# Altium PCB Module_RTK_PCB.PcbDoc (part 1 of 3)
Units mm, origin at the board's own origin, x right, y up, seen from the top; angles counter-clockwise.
Board outline 99.98 x 60 mm, 4 copper layers (Top Layer, gnd, vcc, Bottom Layer), stack 1.536 mm thick; 168 components, 121 nets, 582 pads, 666 vias.
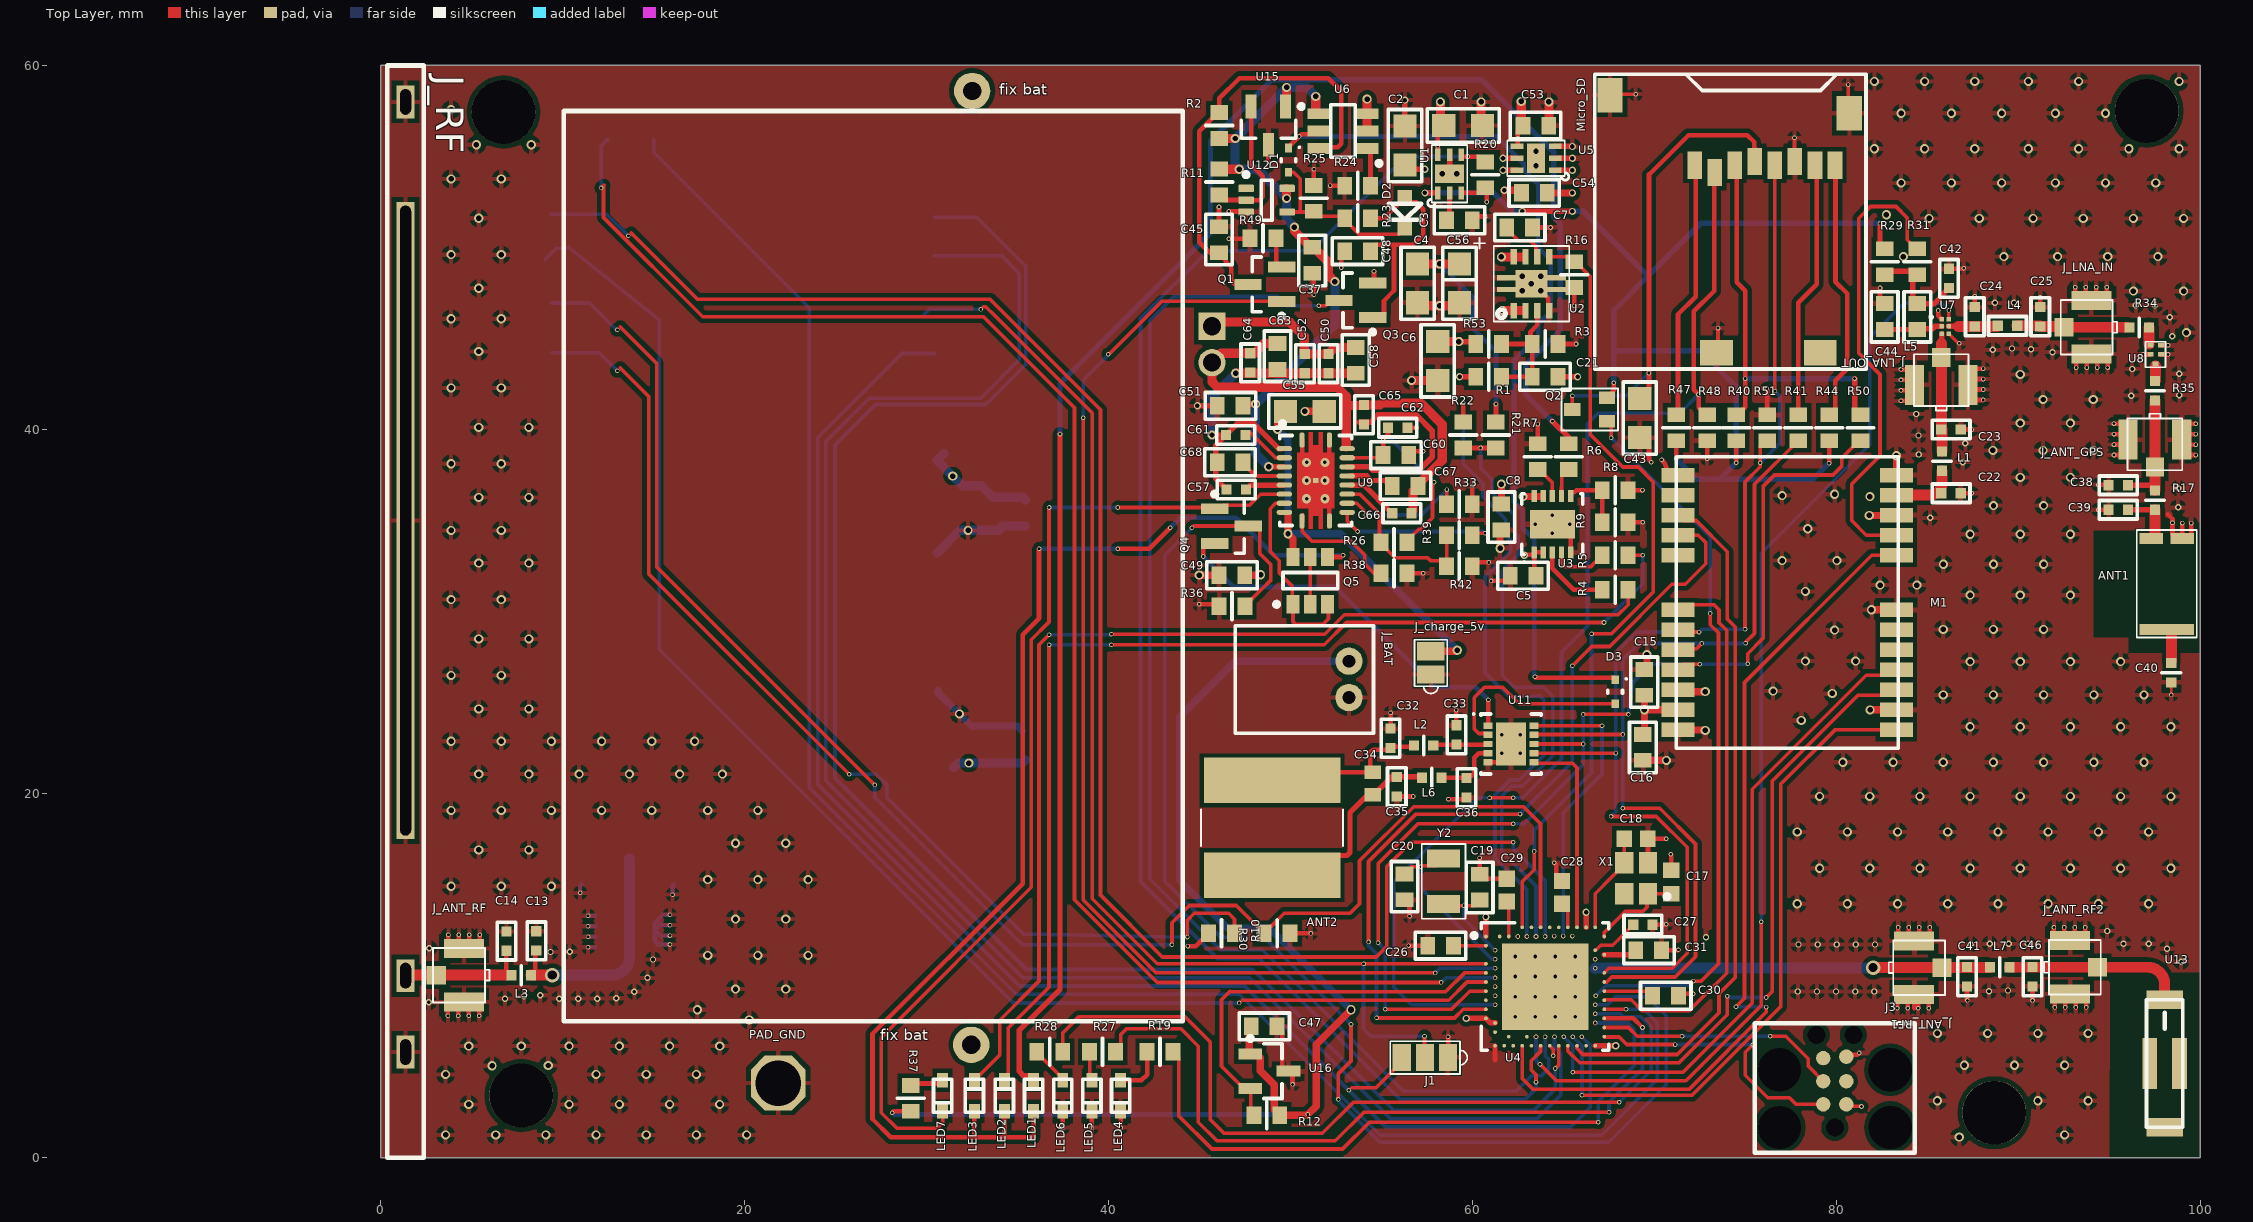
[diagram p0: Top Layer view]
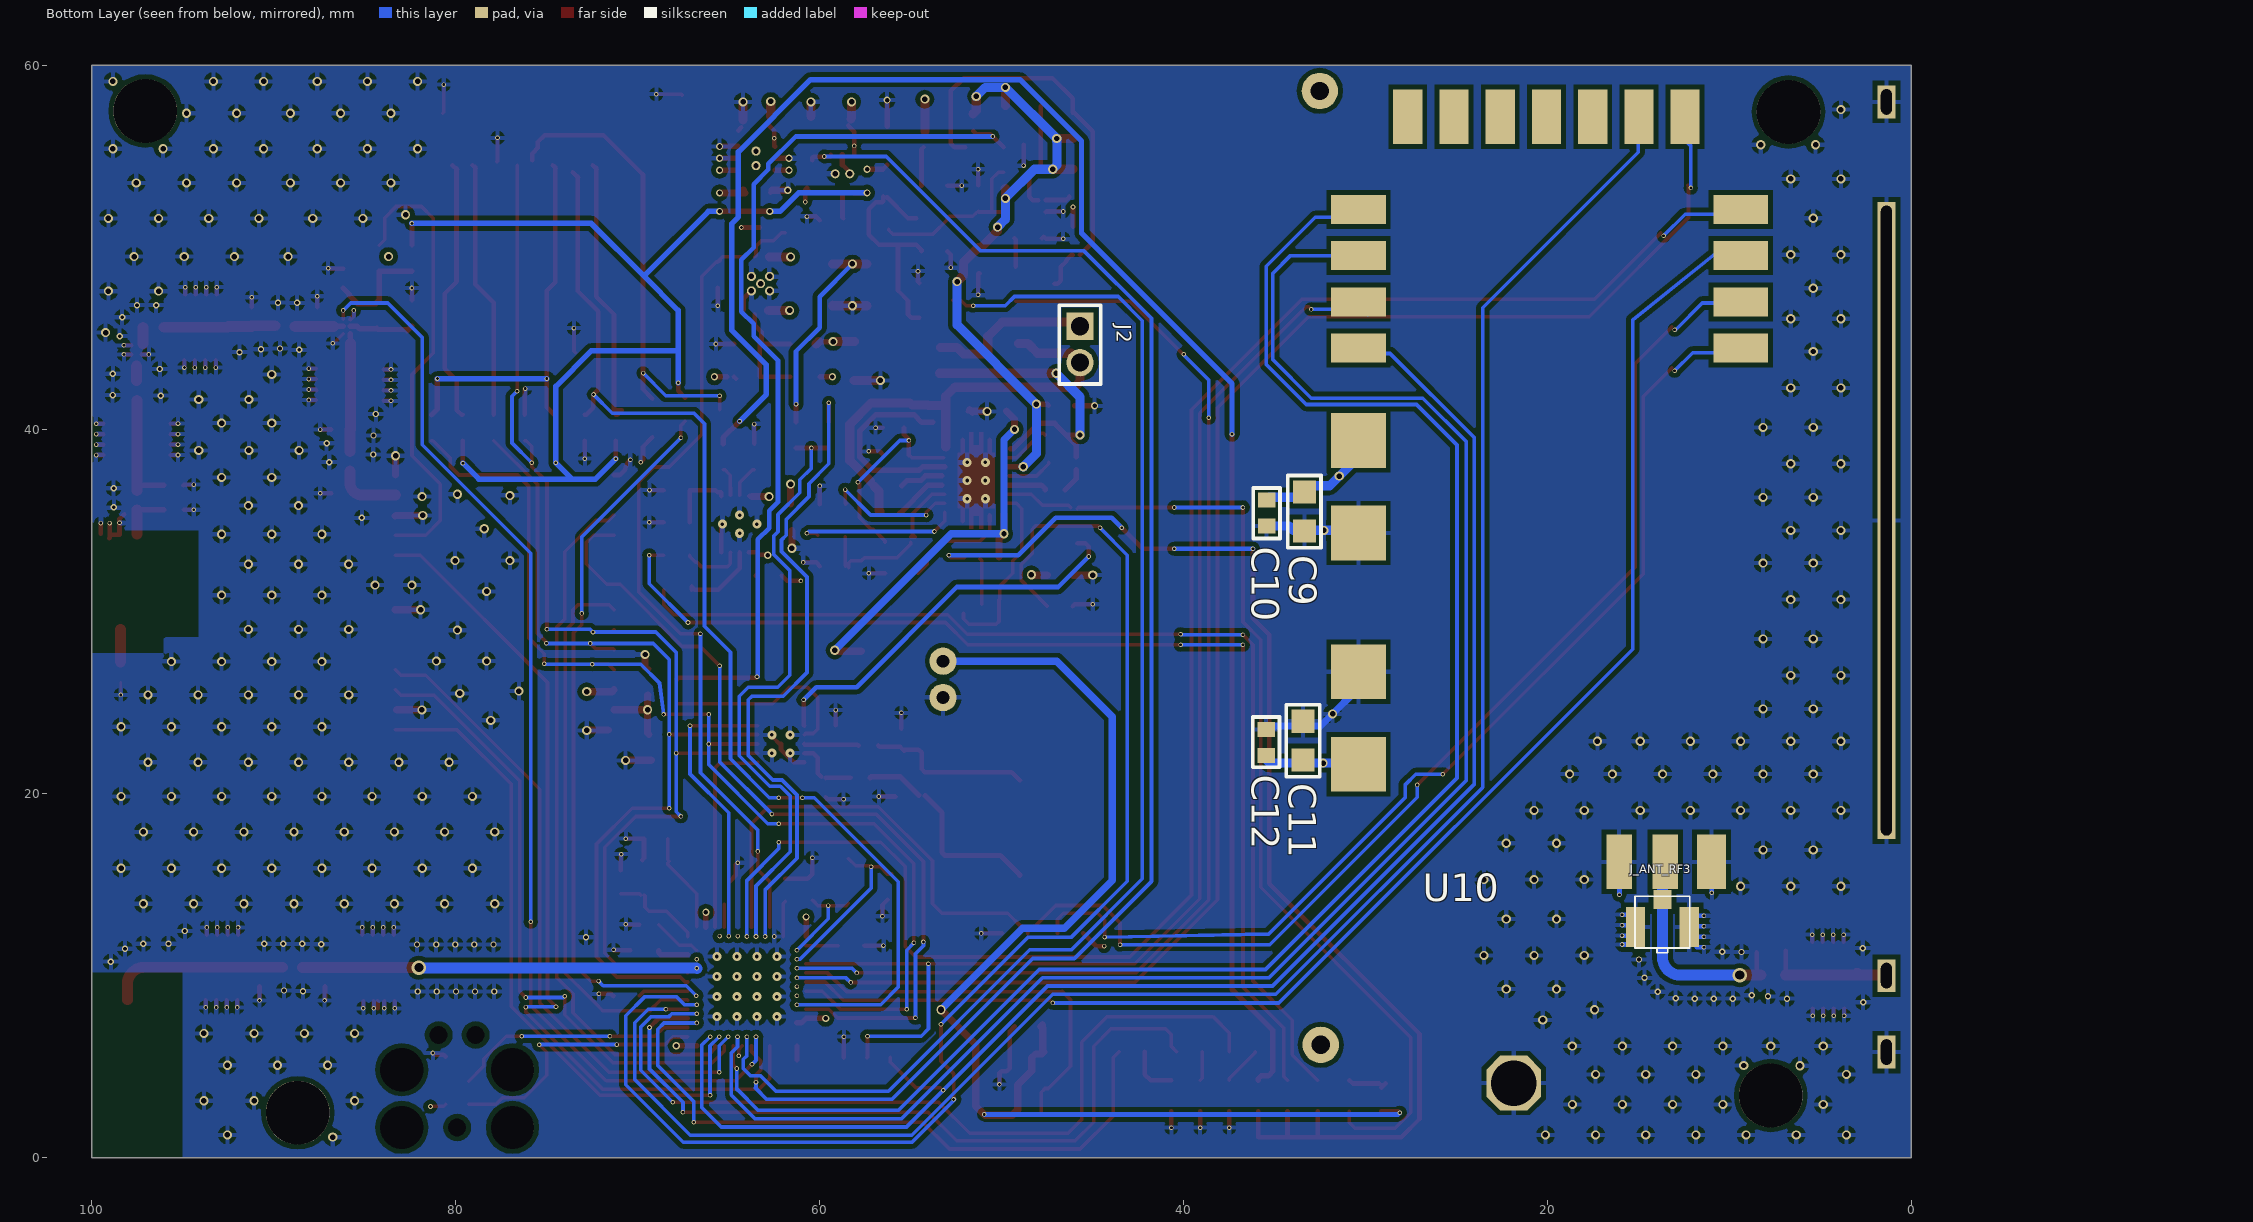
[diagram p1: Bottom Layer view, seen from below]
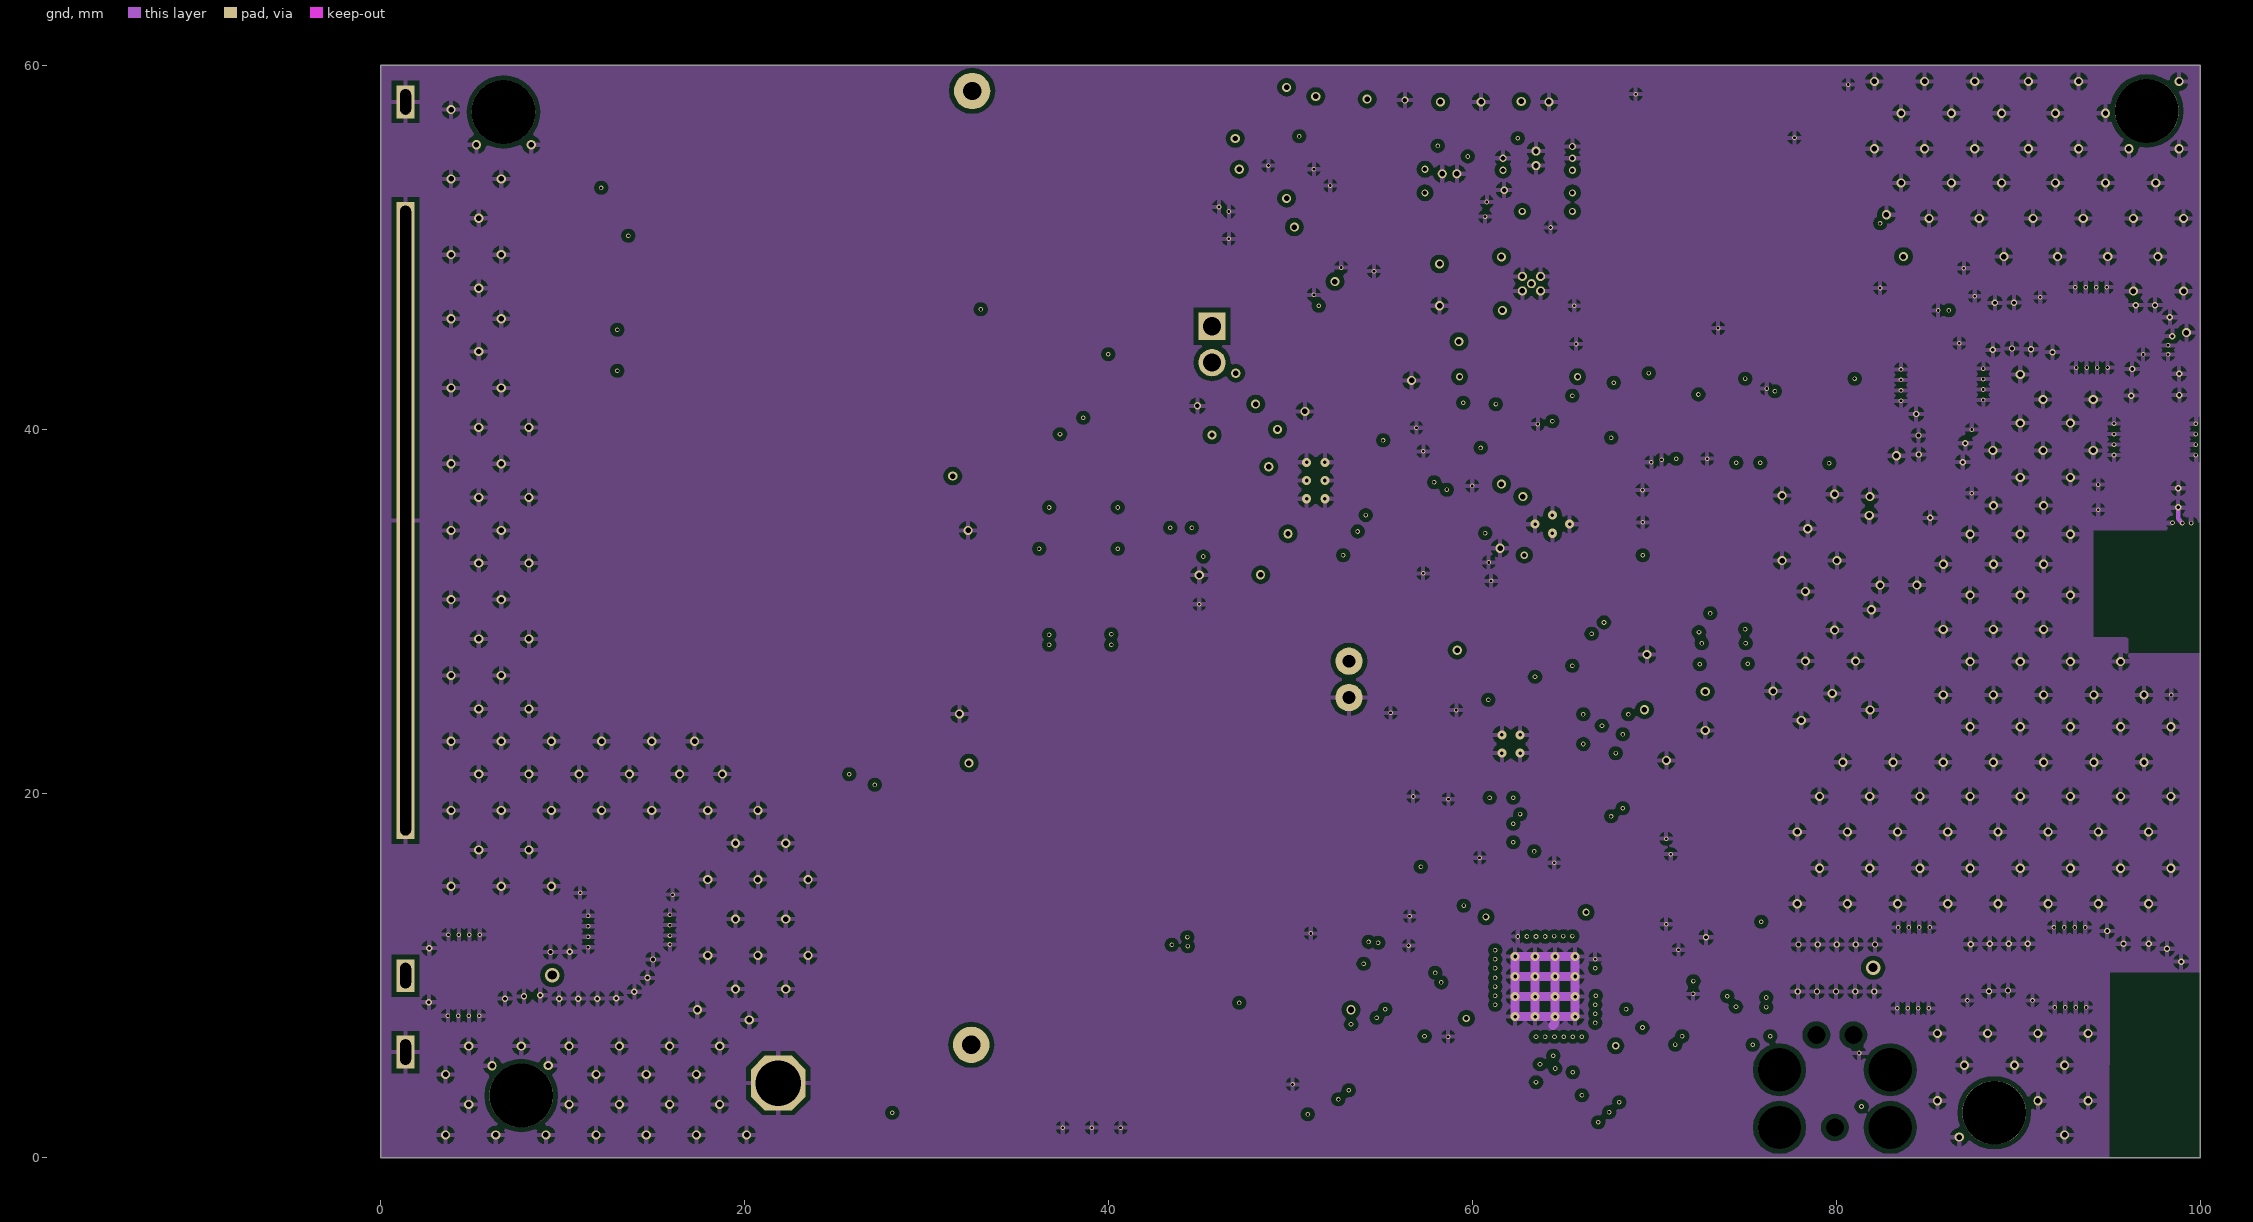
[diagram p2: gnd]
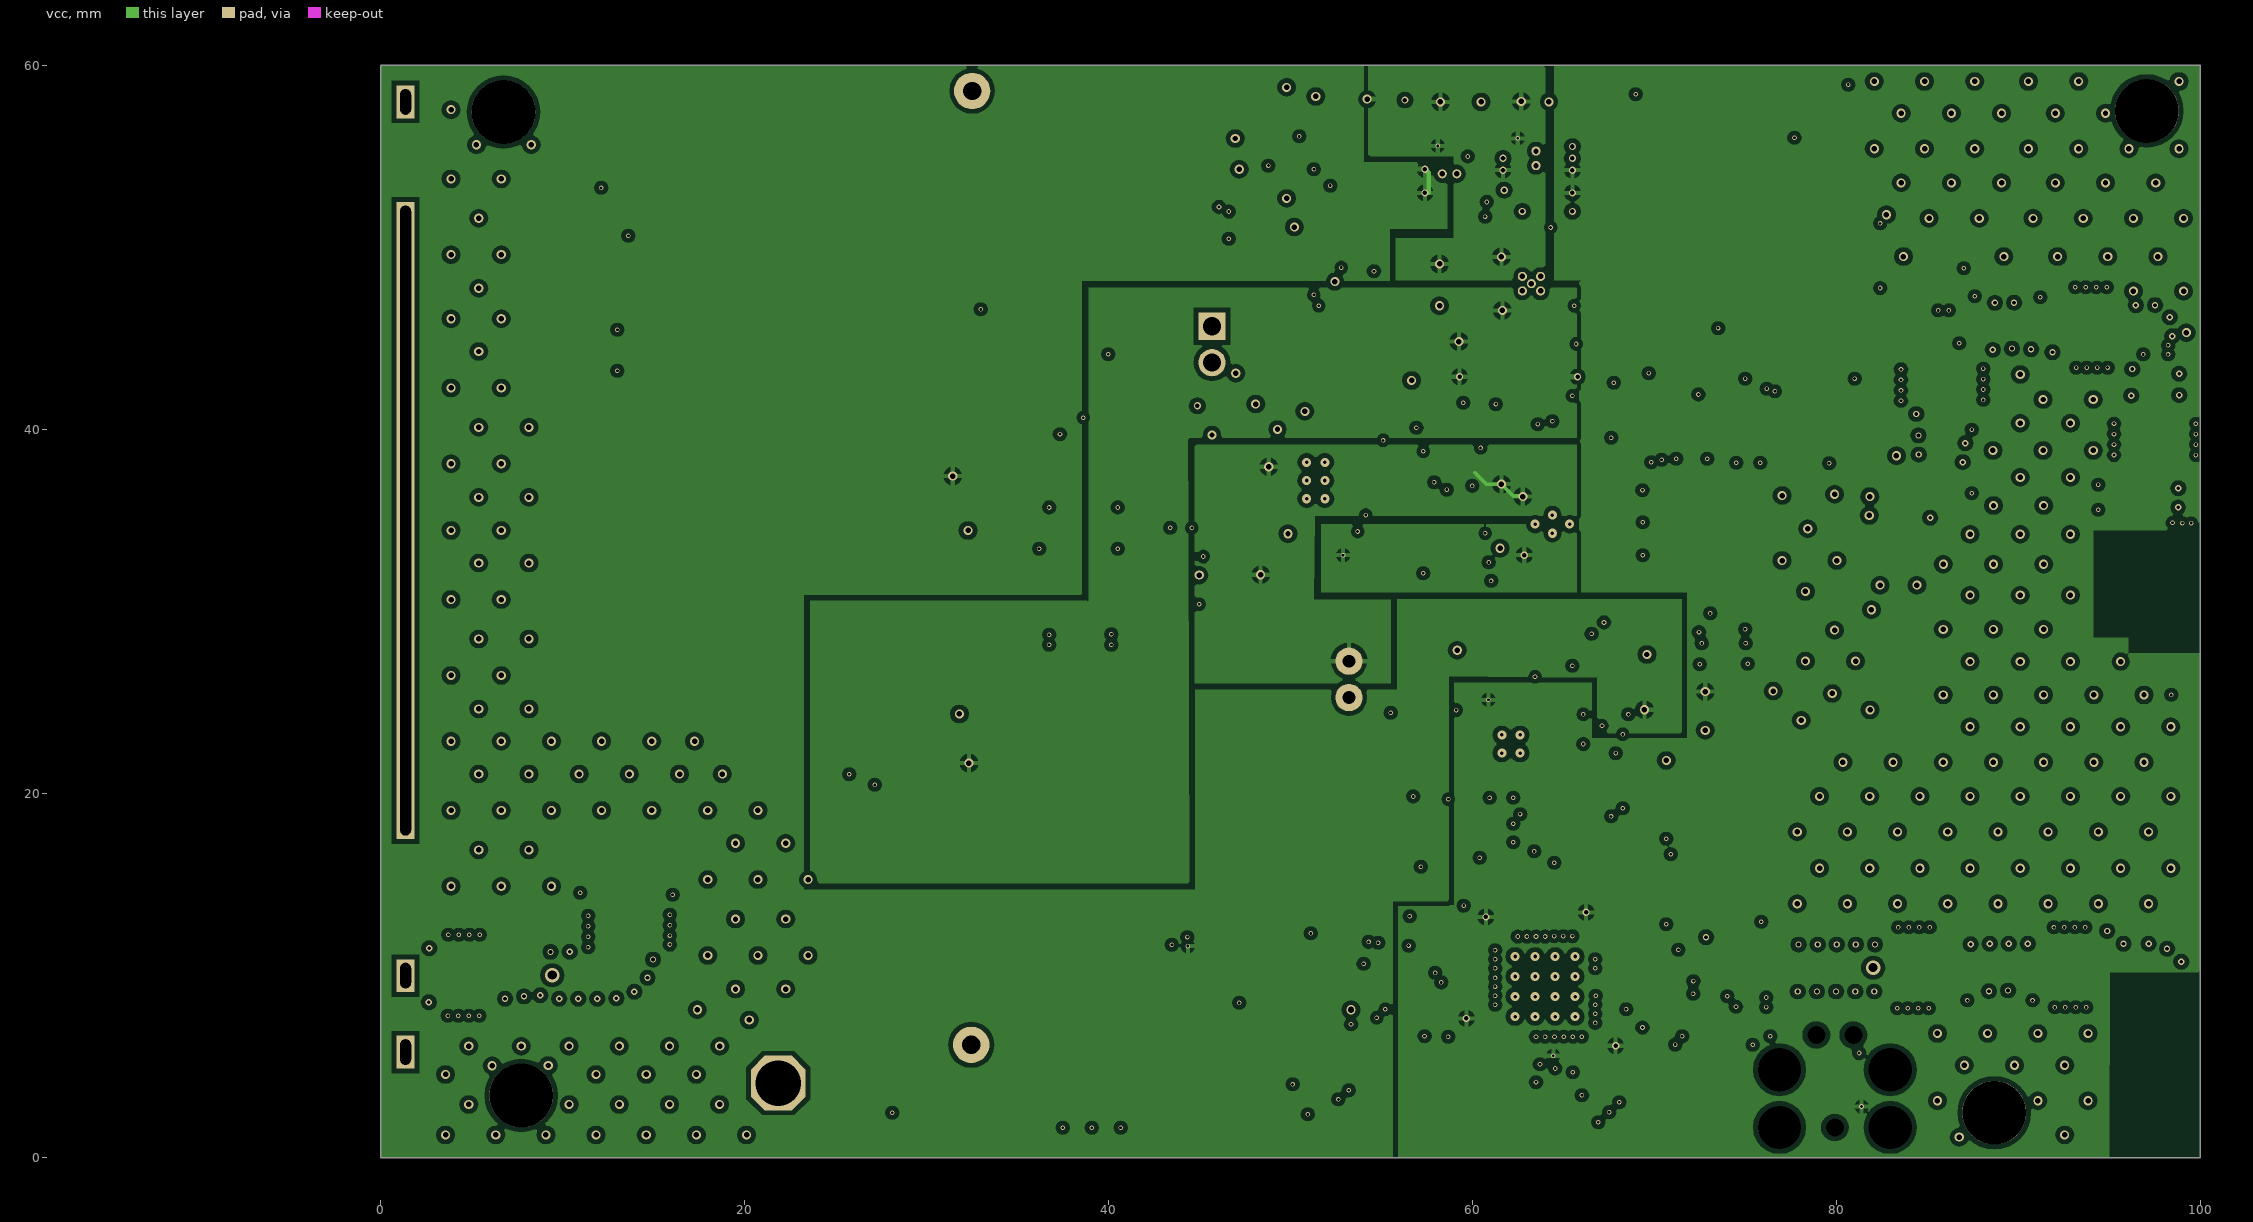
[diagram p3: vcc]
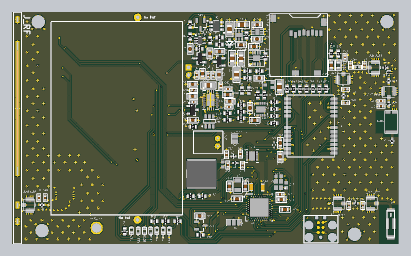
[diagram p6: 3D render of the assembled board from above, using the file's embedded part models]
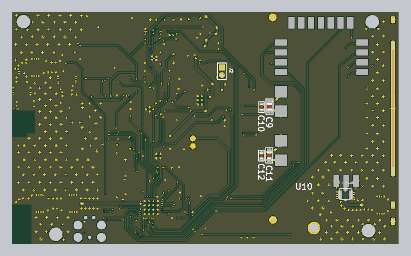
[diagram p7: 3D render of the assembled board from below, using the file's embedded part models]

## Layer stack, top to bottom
Top Solder: solder mask 0.01, Solder Resist, Dk 3.5
Top Layer: signal copper 0.018
Dielectric 2: prepreg 0.36, PP-006, Dk 3.9
gnd: signal copper 0.035
Dielectric 1: dielectric 0.71, FR-4, Dk 3.9
vcc: signal copper 0.035
Dielectric 3: prepreg 0.36, PP-006, Dk 3.9
Bottom Layer: signal copper 0.018
Bottom Solder: solder mask 0.01, Solder Resist, Dk 3.5

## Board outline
0,0 99.975,0 99.975,60 0,60
cut-out: -261.964,-109.154

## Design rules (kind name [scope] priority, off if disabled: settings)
Clearance Clearance_2 [InNet('NetC41_2') vs InNet('NetC46_2')] p1: gap=0.214 ignorepadtopadclearanceinfootprint=FALSE // pour ligne 50ohms de 600um (BLE)
Clearance Clearance_3 [InNet('AG_1') vs InNet('AG_2')] p2: gap=0.214 ignorepadtopadclearanceinfootprint=FALSE // pour ligne 50ohms de 600um (GPS)
Clearance Clearance_4 [InNet('AG_3') vs InNet('AG_4')] p3: gap=0.214 ignorepadtopadclearanceinfootprint=FALSE // pour ligne 50ohms de 600um (GPS)
Clearance Clearance_5 [InNet('AG_5') vs InNet('AG_6')] p4: gap=0.214 ignorepadtopadclearanceinfootprint=FALSE // pour ligne 50ohms de 600um (GPS)
Clearance Clearance_6 [InNet('AG_7') vs InNet('AG_8')] p5: gap=0.214 ignorepadtopadclearanceinfootprint=FALSE // pour ligne 50ohms de 600um (GPS)
Clearance Clearance_7 [InNet('NetANT1_3')] p6: gap=0.214 ignorepadtopadclearanceinfootprint=FALSE // pour ligne 50ohms de 600um (GPS)
Clearance Clearance_1 [InNet('ANT_1') vs InNet('ANT_2')] p7: gap=0.214 ignorepadtopadclearanceinfootprint=FALSE // pour ligne 50ohms de 600um (RF)
Clearance "Stitching GND" [IsStitchingVia and InNet('GND') vs (IsVia and (Not IsStitchingVia)) Or IsPad] p8: gap=0.214 ignorepadtopadclearanceinfootprint=FALSE
Clearance [All] p9: gap=0.254 ignorepadtopadclearanceinfootprint=FALSE except(0: Arc-Hole Track-Hole SMDPad-Hole THPad-Hole Via-Hole Fill-Hole Poly-Hole Region-Hole Text-Hole)
HoleSize [All] p1: absolutevalues=TRUE maxlimit=50 minlimit=0.025 maxpercent=80.000 minpercent=20.000
PolygonConnect [All] p1: connectstyle=Relief reliefconductorwidth=0.254 reliefentries=4 polygonreliefangle="90 Angle" airgapwidth=0.254
RoutingVias [All] p1: holewidth=0.15 width=0.25 viastyle="Through Hole" minholewidth=0.15 minwidth=0.25 maxholewidth=0.711 maxwidth=1.27
SolderMaskExpansion [All] p1: expansion=0.102
Width [All] p1 off: maxlimit=1.5 minlimit=0.2 preferedwidth=0.2
29 further rules are at their usual default settings.

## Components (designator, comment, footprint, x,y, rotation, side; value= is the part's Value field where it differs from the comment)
ANT1 "Taoglas-GLA.01" Taoglas-GLA.01 98.975,34.025 r270 top
ANT2 "W3102" W3102 48.975,18.125 r90 top
C1 "C-1uF-0805" SM/C_0805 59.475,56.7 r180 top value=1uF
C2 "C-2.2uF-0805" SM/C_0805 56.275,55.6 r270 top value=2.2uF
C3 "C-10nF-0603" SM/C_0603 59.264,51.5 r180 top value=10nF
C4 "C-1uF-0805" SM/C_0805 56.975,48.033 r90 top value=1uF
C5 "C-10uF-0603" SM/C_0603 62.769,31.971 r0 top value=10uF
C6 "C-4.7uF-0805" SM/C_0805 58.075,43.767 r90 top value=4.7uF
C7 "C-470nF-0603" SM/C_0603 62.575,51.1 r180 top value=470nF
C8 "C-10uF-0603" SM/C_0603 61.575,35.2 r90 top value=10uF
C9 "C-47uF-0805" SM/C_0805 33.35,35.492 r90 bottom value=47uF
C10 "C-100pF-0603" SM/C_0603 35.425,35.414 r90 bottom value=100pF
C11 "C-47uF-0805" SM/C_0805 33.425,22.906 r270 bottom value=47uF
C12 "C-100pF-0603" SM/C_0603 35.45,22.811 r270 bottom value=100pF
C13 "C-nc-0402" SM/C_0402 8.558,11.908 r270 top value=nc
C14 "C-nc-0402" SM/C_0402 6.912,11.9 r270 top value=nc
C15 "C-10uF-0603" SM/C_0603 69.425,26.111 r270 top value=10uF
C16 "C-100nF-0603" SM/C_0603 69.35,22.539 r90 top value=100nF
C17 "8pf" CAPC1608X90X35LL15T15 70.9,15.15 r90 top
C18 "8pf" CAPC1608X90X35LL15T15 68.975,17.525 r180 top
C19 "C-12pF-0603-2%-NP0" SM/C_0603 60.375,14.861 r90 top value=12pF
C20 "C-12pF-0603-2%-NP0" SM/C_0603 56.25,14.875 r270 top value=12pF
C21 "C-470nF-0603" SM/C_0603 63.975,42.9 r0 top value=470nF
C22 "C-nc-0402" SM/C_0402 86.275,36.5 r180 top value=nc
C23 "C-nc-0402" SM/C_0402 86.275,40 r180 top value=nc
C24 "C-nc-0402" SM/C_0402 87.575,46.2 r270 top value=nc
C25 "C-nc-0402" SM/C_0402 91.175,46.2 r270 top value=nc
C26 "C-100nF-0603" SM/C_0603 58.239,11.65 r0 top value=100nF
C27 "C-100pF 0402 NPO 5%" SM/C_0402 69.35,12.8 r0 top value=100pF
C28 "nc" CAPC1709X95X35LL10T25 64.9,14.575 r270 top
C29 "1uF" CAPC1709X95X35LL10T25 61.875,14.7 r270 top
C30 "C-100nF-0603" SM/C_0603 70.589,8.9 r180 top value=100nF
C31 "C-100nF-0603" SM/C_0603 69.664,11.4 r180 top value=100nF
C32 "C-nc-0402" SM/C_0402 55.487,23.037 r270 top value=nc
C33 "C-nc-0402" SM/C_0402 59.1,23.225 r270 top value=nc
C34 "06032U8R2CAT2A" CAPC1508X91X25LL25T13 54.5,20.545 r90 top value=8.2pf
C35 "C-nc-0402" SM/C_0402 55.825,20.375 r90 top value=nc
C36 "C-nc-0402" SM/C_0402 59.65,20.325 r90 top value=nc
C37 "C-100nF-0603" SM/C_0603 51.175,49.3 r90 top value=100nF
C38 "C-2.7pF-0402" SM/C_0402 95.467,36.938 r0 top value=2.7pF
C39 "C-nc-0402" SM/C_0402 95.467,35.592 r0 top value=nc
C40 "R-0-0402" SM/R_0402 98.375,26.642 r90 top value=0
C41 "C-nc-0402" SM/C_0402 87.15,9.938 r90 top value=nc
C42 "C-100pF-0402" SM/C_0402 86.154,48.3 r90 top value=100pF
C43 "C-47uF-0805" SM/C_0805 69.175,40.633 r90 top value=47uF
C44 "C-1uF-0603" SM/C_0603 82.625,46.207 r90 top value=1uF
C45 "C-10uF-0603" SM/C_0603 46.061,50.426 r270 top value=10uF
C46 "C-nc-0402" SM/C_0402 90.75,9.938 r90 top value=nc
C47 "C-100nF-0603" SM/C_0603 48.54,7.209 r180 top value=100nF
C48 "C-10uF-0603" SM/C_0603 53.675,49.8 r0 top value=10uF
C49 "C-100nF-0603" SM/C_0603 46.764,32 r180 top value=100nF
C50 "C-68n 0402 X7R" SM/C_0402 52.075,43.625 r270 top value=68n
C51 "C-4.7uF-0603" SM/C_0603 46.675,41.3 r180 top value=4.7uF
C52 "C-68n 0402 X7R" SM/C_0402 50.775,43.625 r270 top value=68n
C53 "C-1uF-0603" SM/C_0603 63.464,56.7 r0 top value=1uF
C54 "C-1uF-0603" SM/C_0603 63.386,53 r0 top value=1uF
C55 "C-1uF-0805" SM/C_0805 50.775,41 r180 top value=1uF
C56 "C-22uF-0805-6.3V-TANT" SM/C_0805_POL 59.275,48.033 r270 top value=22uF
C57 "C-22n 0402 X7R" SM/C_0402 47.008,36.7 r0 top value=22n
C58 "C-47n 0603 X7R" SM/C_0603 53.575,43.803 r270 top value=47n
C60 "C-4.7u 0603 X5R 16V" SM/C_0603 55.775,38.6 r180 top value=4.7u
C61 "C-10nF 0402 X7R 5%" SM/C_0402 46.975,39.7 r0 top value=10nF
C62 "C-22n 0402 X7R 16V" SM/C_0402 55.875,40.1 r180 top value=22n
C63 "C-1800pF 0603 NPO 5%" SM/C_0603 49.275,44.014 r270 top value=1800pF
C64 "C-100pF 0402 NPO 5%" SM/C_0402 47.775,43.658 r270 top value=100pF
C65 "C-10nF 0402 X7R 5%" SM/C_0402 54.025,40.818 r270 top value=10nF
C66 "C-22n 0402 X7R" SM/C_0402 56.108,35.4 r180 top value=22n
C67 "C-470nF-0603" SM/C_0603 56.286,36.9 r180 top value=470nF
C68 "C-470nF-0603" SM/C_0603 46.675,38.2 r0 top value=470nF
D1 "RB521S30T1G" ONSC-SOD-523-2-502-01_V 49.875,54.8 r270 top
D2 "D-CDSU4148-0603" 0603/SOD-523F_Diode 56.275,51.9 r270 top
D3 "RB521S30T1G" ONSC-SOD-523-2-502-01_V 67.825,25.6 r270 top
J1 "FTDI" SINGLE_3_1.27mm 58.645,5.5 r180 top
J2 "J-7.5uH  28X15mm Wurth 760308103206" WE-WPCC 45.675,45.675 r270 bottom
J3 "TC2030-CTX" TC2030-IDC 79.89,1.66 r90 top
J_ANT_GPS "U.FL-R-SMT" U.FL-R-SMT 97.475,37.938 r0 top
J_ANT_RF "U.FL-R-SMT" U.FL-R-SMT 3.058,10.025 r270 top
J_ANT_RF1 "U.FL-R-SMT" U.FL-R-SMT 85.776,10.438 r90 top
J_ANT_RF2 "U.FL-R-SMT" U.FL-R-SMT 94.325,10.463 r90 top
J_ANT_RF3 "U.FL-R-SMT" U.FL-R-SMT 13.684,14.187 r0 bottom
J_BAT "S2B-PH-K-S" S2B-PH-K-S 53.2,25.275 r90 top
J_charge_5v "charge 5v optionnel (fil a souder)" "2 pads soudable" 57.7,26.55 r90 top
J_LNA_IN "U.FL-R-SMT" U.FL-R-SMT 92.475,45.621 r270 top
J_LNA_OUT "U.FL-R-SMT" U.FL-R-SMT 85.742,43.965 r180 top
J_RF "FTDI" "connecteur ant RF" 2.375,0 r90 top
L1 "R-0-0402" SM/R_0402 85.775,38.267 r90 top value=0
L2 "R-0-0402" SM/R_0402 57.3,22.64 r0 top value=0
L3 "R-0-0402" SM/R_0402 7.725,10.025 r180 top value=0
L4 "L-4.7nH-0402" SM/L_0402 89.375,45.7 r0 top value=4.7nH
L5 "Lfe-60R-0603-1.2A" "SM/L_0603 (1608)" 84.425,46.207 r90 top value=Beads
L6 "R-0-0402" SM/R_0402 57.742,20.875 r0 top value=0
L7 "R-0-0402" SM/R_0402 88.95,10.463 r0 top value=0
LED1 "LED-RED-0603" SM/D_0603 35.875,3.4 r270 top
LED2 "LED-GREEN-0603" SM/D_0603 34.275,3.4 r270 top
LED3 "LED-ORANGE-0603" SM/D_0603 32.625,3.4 r270 top
LED4 "LED-RED-0603" SM/D_0603 40.654,3.4 r90 top
LED5 "LED-GREEN-0603" SM/D_0603 39.075,3.4 r90 top
LED6 "LED-AMBER-0603-HI_BRIGHT" SM/D_0603 37.475,3.4 r90 top
LED7 "LED-RED-0603" SM/D_0603 30.875,3.4 r90 top
M1 "NEO-M8P NEW!!" NEO-7 71.175,22.5 r0 top
Micro_SD "Micro_SD-Push_Push" Amphenol-10100660 72.2,54.525 r0 top
PAD_GND "Test_PAD_HOLE_3x3mm" Test_PAD_HOLE_3x3mm 21.85,4.1 r90 top
Q1 "BSS138" SOT23_0.915 48.583,47.975 r180 top
Q2 "PMOS" SOT-323 66.425,41.1 r90 top
Q3 "BSS138" SOT23_0.915 53.575,47.1 r180 top
Q4 "IRLML6402PBF" SOT23_0.915 46.75,34.7 r0 top
Q5 "FDC6304P" supersot_6 51.075,31.7 r90 top
R1 "R-62k-0603-0.1%" SM/R_0603 60.875,42.9 r180 top value=62k
R2 "R-100k-0603" SM/R_0603 46.075,56.7 r270 top value=100k
R3 "R-10k-0603-0.1%" SM/R_0603 63.975,44.7 r180 top value=10k
R4 "R-2.7k-0603" SM/R_0603 67.825,31.2 r180 top value=2.7k
R5 "R-2.7k-0603" SM/R_0603 67.825,33.1 r180 top value=2.7k
R6 "R-2.7k-0603" SM/R_0603 65.275,38.511 r270 top value=2.7k
R7 "R-10k-0603-0.1%" SM/R_0603 63.575,38.511 r270 top value=10k
R8 "R-10k-0603-0.1%" SM/R_0603 67.825,36.675 r180 top value=10k
R9 "R-10k-0603-0.1%" SM/R_0603 67.825,34.9 r180 top value=10k
R10 "R-10k-0603" SM/R_0603 46.2,12.323 r180 top value=10k
R11 "R-10k-0603" SM/R_0603 46.075,53.6 r270 top value=10k
R12 "R-10k-0603" SM/R_0603 48.689,2.325 r180 top value=10k
R16 "R-100k-0603" SM/R_0603 65.575,48.511 r90 top value=100k
R17 "R-0-0402" SM/R_0402 97.475,36.125 r270 top value=0
R19 "R-470-0603" SM/R_0603 42.822,5.825 r0 top value=470
R20 "R-100k-0603" SM/R_0603 60.675,53.989 r90 top value=100k
R21 "R-100k-0603-0.1%" SM/R_0603 61.275,39.7 r90 top value=100k
R22 "R-100k-0603-0.1%" SM/R_0603 59.475,39.7 r270 top value=100k
R23 "R-390k-0603" SM/R_0603 53.675,51.6 r180 top value=390k
R24 "R-10k-0603" SM/R_0603 53.675,53.4 r0 top value=10k
R25 "R-10k-0603" SM/R_0603 51.275,52.7 r90 top value=10k
R26 "R-20k-0603" SM/R_0603 55.675,33.8 r180 top value=20k
R27 "R-470-0603" SM/R_0603 39.664,5.825 r0 top value=470
R28 "R-100-0603" SM/R_0603 36.764,5.825 r0 top value=100
R29 "R-nc" SM/R_0603 82.625,49.218 r90 top value=nc
R30 "R-10k-0603" SM/R_0603 49.251,12.319 r180 top value=10k
R31 "R-0-0603" SM/R_0603 84.425,49.218 r270 top value=0
R33 "R-10k-0603" SM/R_0603 59.264,35.9 r0 top value=10k
R34 "R-0-0402" SM/R_0402 96.608,45.6 r0 top value=0
R35 "R-0-0402" SM/R_0402 97.475,42.125 r270 top value=0
R36 "R-470k-0603" SM/R_0603 46.775,30.3 r0 top value=470k
R37 "R-2.7k-0603" SM/R_0603 29.125,3.261 r270 top value=R-2.7k
R38 "R-2.43k-0603" SM/R_0603 55.675,32.1 r180 top value=2.43k
R39 "R-422-0603" SM/R_0603 59.264,34.2 r180 top value=422
R40 "R-10k-0603" SM/R_0603 74.475,40.1 r270 top value=10k
R41 "R-100-0603" SM/R_0603 77.875,40.1 r90 top value=100
R42 "R-200-0603" SM/R_0603 59.264,32.5 r180 top value=200
R44 "R-100k-0603" SM/R_0603 79.575,40.1 r90 top value=100k
R47 "R-100k-0603" SM/R_0603 71.175,40.1 r90 top value=100k
R48 "R-1M-0603" SM/R_0603 72.875,40.1 r270 top value=1M
R49 "R-10k-0603" SM/R_0603 48.475,50.5 r180 top value=10k
R50 "R-47-0603" SM/R_0603 81.3,40.1 r90 top value=47
R51 "R-1M-0603" SM/R_0603 76.175,40.1 r270 top value=1M
R53 "R-62k-0603-0.1%" SM/R_0603 60.875,44.7 r180 top value=62k
U1 "TPS73430DRV" SON-6_DRV 58.075,53 r90 top
U2 "TPS7A8101" SON-8_DRB 62.25,46.537 r90 top
U3 "MCP73833" DFN-MF10 64.375,34.8 r90 top
U4 "NRF52840-QIAA-R7" NRSC-AQFN-73 63.975,9.4 r0 top
U5 "TPS78230DRV" SON-6_DRV 64.525,54.25 r180 top
U6 "FDC6330L" SOT-363_0.95 52.875,56.4 r180 top
U7 "BGA725L6" INF-TSLP-6-2_V 85.954,45.667 r0 top
U8 "B9415" B9415 97.515,43.625 r90 top
U9 "BQ51050BRHLR" RHL20-3050X2050TP 51.375,37.2 r0 top
U10 "Module_RF_EXT_IO_4_2" Module_RF4_2 9.375,57.175 r270 bottom
U11 "AS3953A" MLPD_3x3mm_10_pin_AS3953A 62.1,22.725 r0 top
U12 "SN74LVC1G04DCKR" DCK0005A_N 48.675,52.6 r0 top
U13 "2450AT43B100" 2450AT43B100 98.01,5.176 r90 top
U15 "DRV5021" SOT23 48.775,56.7 r270 top
U16 "DRV5021" SOT23 48.825,4.75 r0 top
X1 "CX2520DB32000D0GEJZ1" AVX-CX2520DB32000D0GEJZ1-4_V 68.975,15.35 r180 top
Y2 "32.768kHz - 20ppm - CTS-TF32" CTS-TF32 58.4,15.18 r90 top

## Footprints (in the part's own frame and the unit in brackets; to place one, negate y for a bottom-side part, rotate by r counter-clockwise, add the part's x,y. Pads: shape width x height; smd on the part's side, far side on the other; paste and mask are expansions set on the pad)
"2 pads soudable" [mm] "Connector; Header; 2 Position"
  rect 1x1.5 smd: 1(0,0) 2(1.27,0)
  silkscreen extent -1.05,-0.9 1.91,0.9
0603/SOD-523F_Diode [mm] "SODFL, 2-Leads, Body 0,90x1,70mm, IPC Medium Density"
  rect 0.8x0.8 smd: 1(-0.85,0) 2(0.85,0)
  silkscreen extent -0.51,-0.89 0.38,0.89, body extent -0.9,-0.5 0.9,0.5, height 0.85
2450AT43B100 [mm] "ble ant 2.4 GHz"
  rect 1x2 smd: 1(3.5,0) 2(-3.5,0)
  rect 2.8x0.8 smd: 3(0,0.815) 4(0,-0.815)
  silkscreen extent -3.5,-1 3.5,1
Amphenol-10100660 [mm] "Micro-SD"
  rect 1.4x1.9 smd: 0(-4.66,3.85) 0(8.49,2.85)
  rect 1.8x1.4 smd: 0(1.19,-10.3) 9(6.89,-10.3)
  rect 0.8x1.5 smd: 1(0,0) 2(1.1,-0.4) 3(2.2,0) 4(3.3,0.2) 5(4.4,0) 6(5.5,0.2) 7(6.6,0) 8(7.7,0)
  silkscreen extent -5.5,-11.2 9.4,5
AVX-CX2520DB32000D0GEJZ1-4_V [mm] "Hand Drawn, 4-Leads,Body 2.5x2mm"
  rect 1x1.2 smd: 1(-0.65,0.85) 2(-0.65,-0.85) 3(0.65,-0.85) 4(0.65,0.85)
  silkscreen extent -1.83,0.88 -1.58,1.12, body extent -1,-1.25 1,1.25, height 0.55
B9415 [mm]
  rect 0.25x0.325 smd: 1(0,0) 2(0.5,-0.288) 3(1,-0.288) 4(1,0.288) 5(0.5,0.288)
  silkscreen extent -0.2,-0.55 1.2,0.55
CAPC1508X91X25LL25T13 [mm] "Chip Capacitor, 2-Leads, Body 1.52x0.76mm, IPC High Density"
  rect 0.74x0.92 smd: 1(-0.62,0) 2(0.62,0)
  body extent -0.88,-0.51 0.89,0.51, height 0.91
CAPC1608X90X35LL15T15 [mm] "Chip Capacitor, 2-Leads, Body 1.60x0.81mm, IPC High Density"
  rect 0.85x0.9 smd: 1(-0.65,0) 2(0.65,0)
  body extent -0.88,-0.48 0.87,0.48, height 0.9
CAPC1709X95X35LL10T25 [mm] "Chip Capacitor, 2-Leads, Body 1.75x0.95mm, IPC High Density"
  rect 0.9x0.9 smd: 1(-0.625,0) 2(0.625,0)
  body extent -0.87,-0.48 0.87,0.48, height 0.95
"connecteur ant RF" [mm]
  rect 1.8x1 hole 0.6 slot 1.4 at 0 deg: 1(10,1) 2(5.8,1) 3(58,1)
  rect 35x1 hole 0.6 slot 34.6 at 0 deg: 2(35,1)
  silkscreen extent 0,0 60,2
CTS-TF32 [mm] "3.2mm x 1.5mm"
  rect 1x1.8 smd: 1(-1.25,0) 2(1.25,0)
  silkscreen extent -2.05,-1.2 2.05,1.2
DCK0005A_N [mm] "SOT23, 5-Leads, Body 2.15x1.4mm, Pitch 0.65mm, IPC Medium Density"
  rrect25% 0.85x0.4 smd: 1(-1.125,0.65) 2(-1.125,0) 3(-1.125,-0.65) 4(1.125,-0.65) 5(1.125,0.65)
  silkscreen extent -1.25,-1.1 0.3,1.52, body extent -1.14,-1 1.14,1, height 0.94
DFN-MF10 [mm] "SON, 10-Leads, Body 3x3mm, Pitch 0.5mm, Microchip Recommended"
  rect 1.55x2.48 smd: 0(0,0)
  rect 0.65x0.3 smd: 1(-1.55,1) 2(-1.55,0.5) 3(-1.55,0) 4(-1.55,-0.5) 5(-1.55,-1) 6(1.55,-1) 7(1.55,-0.5) 8(1.55,0) 9(1.55,0.5) 10(1.55,1)
  silkscreen extent -2.12,-1.68 1.67,1.68, body extent -1.52,-1.52 1.52,1.52, height 1
INF-TSLP-6-2_V [mm] "TSLP, 6-Leads, Body 0.7x1.1 mm"
  rect 0.25x0.25 smd: 1(-0.2,0.4) 2(-0.2,0) 3(-0.2,-0.4) 4(0.2,-0.4) 5(0.2,0) 6(0.2,0.4)
  silkscreen extent -0.8,0.48 -0.75,0.53, body extent -0.35,-0.55 0.35,0.55, height 0.4
MLPD_3x3mm_10_pin_AS3953A [mm] "PSON, 10-Leads, Body 3,00x3,00mm, Pitch 0,50mm, Thermal Pad 2,36x1,63mm, IPC Medium Density"
  rect 0.5x0.35 smd: 1(-1.27,1) 2(-1.27,0.5) 3(-1.27,0) 4(-1.27,-0.5) 5(-1.27,-1) 6(1.27,-1) 7(1.27,-0.5) 8(1.27,0) 9(1.27,0.5) 10(1.27,1)
  rect 1.63x2.36 smd: 11(0,0)
  silkscreen extent -2.1,-1.65 1.65,1.7, body extent -1.5,-1.5 1.5,1.5, height 1
Module_RF4_2 [mm]
  rect 3x3 smd: 1(35.56,-21) 2(30.48,-21) 3(22.86,-21) 4(17.78,-21)
  rect 1.6x3 smd: 5(12.7,-21) 6(10.16,-21) 7(7.62,-21) 8(5.08,-21) 16(5.08,0) 17(7.62,0) 18(10.16,0) 19(12.7,0)
  rect 3x1.6 smd: 9(0,-18.296) 10(0,-15.756) 11(0,-13.216) 12(0,-10.676) 13(0,-8.136) 14(0,-5.596) 15(0,-3.056) 20(40.925,-1.61)
  rect 3x1.4 smd: 21(40.925,-4.15) 22(40.925,-6.69)
  body extent 0.13,-20.96 40.93,0, height 3
NEO-7 [mm] "GNSS module for GPS/QZSS, GLONASS"
  rect 1.8x0.8 smd: 1(12.1,1) 2(12.1,2.1) 3(12.1,3.2) 4(12.1,4.3) 5(12.1,5.4) 6(12.1,6.5) 7(12.1,7.6) 8(12.1,10.6) 9(12.1,11.7) 10(12.1,12.8) 11(12.1,13.9) 12(12.1,15) 13(0.1,15) 14(0.1,13.9) 15(0.1,12.8) 16(0.1,11.7) 17(0.1,10.6) 18(0.1,7.6) 19(0.1,6.5) 20(0.1,5.4) 21(0.1,4.3) 22(0.1,3.2) 23(0.1,2.1) 24(0.1,1)
  silkscreen extent 0,0 12.2,16
NRSC-AQFN-73 [mm] "AQFN, 73-Leads, Body 7x7mm, Pitch 0.5mm"
  rect 4.75x4.75 smd: 74(0,0)
  round 0.2 smd: A8(-1.25,3.25) A10(-0.75,3.25) A12(-0.25,3.25) A14(0.25,3.25) A16(0.75,3.25) A18(1.25,3.25) A20(1.75,3.25) A22(2.25,3.25) A23(2.75,3.25) AA24(3.25,-2.25) AB2(-2.75,-2.5) AC5(-2,-2.75) AC9(-1,-2.75) AC11(-0.5,-2.75) AC13(0,-2.75) AC15(0.5,-2.75) AC17(1,-2.75) AC19(1.5,-2.75) AC21(2,-2.75) AC24(3.25,-2.75) AD2(-2.75,-3.25) AD4(-2.25,-3.25) AD6(-1.75,-3.25) AD8(-1.25,-3.25) AD10(-0.75,-3.25) AD12(-0.25,-3.25) AD14(0.25,-3.25) AD16(0.75,-3.25) AD18(1.25,-3.25) AD20(1.75,-3.25) AD22(2.25,-3.25) AD23(2.75,-3.25) B1(-3.25,2.75) B3(-2.5,2.75) B5(-2,2.75) B7(-1.5,2.75) B9(-1,2.75) B11(-0.5,2.75) B13(0,2.75) B15(0.5,2.75) B17(1,2.75) B19(1.5,2.75) B24(3.25,2.75) C1(-3.25,2.25) D2(-2.75,2) D23(2.75,2) E24(3.25,1.75) F2(-2.75,1.5) F23(2.75,1.5) G1(-3.25,1.25) H2(-2.75,1) H23(2.75,1) J1(-3.25,0.75) J24(3.25,0.75) K2(-2.75,0.5) L1(-3.25,0.25) L24(3.25,0.25) M2(-2.75,0) N1(-3.25,-0.25) N24(3.25,-0.25) P2(-2.75,-0.5) P23(2.75,-0.5) R1(-3.25,-0.75) R24(3.25,-0.75) T2(-2.75,-1) T23(2.75,-1) U1(-3.25,-1.25) U24(3.25,-1.25) V23(2.75,-1.5) W1(-3.25,-1.75) W24(3.25,-1.75) Y2(-2.75,-2) Y23(2.75,-2)
  silkscreen extent -4.02,-3.5 3.5,3.5, body extent -3.5,-3.5 3.5,3.5, height 0.85
ONSC-SOD-523-2-502-01_V [mm] "SOD, 2-Leads, Body 1.2x0.8mm"
  rect 0.48x0.4 smd: 1(-0.66,0) 2(0.66,0)
  silkscreen extent -0.75,-0.4 0.07,0.65, body extent -0.6,-0.4 0.6,0.4, height 0.7
RHL20-3050X2050TP [mm] "QFN, 20-Leads, Body 4.5x3.5mm, Pitch 0.5mm, Thermal Pad 3.05x2.05mm, TI Recommended"
  oval 0.28x0.85 smd paste-0.025 mask+0.07: 1(-0.75,2.225) 10(-0.75,-2.225) 11(0.75,-2.225) 20(0.75,2.225)
  oval 0.85x0.28 smd paste-0.025 mask+0.07: 2(-1.725,1.75) 3(-1.725,1.25) 4(-1.725,0.75) 5(-1.725,0.25) 6(-1.725,-0.25) 7(-1.725,-0.75) 8(-1.725,-1.25) 9(-1.725,-1.75) 12(1.725,-1.75) 13(1.725,-1.25) 14(1.725,-0.75) 15(1.725,-0.25) 16(1.725,0.25) 17(1.725,0.75) 18(1.725,1.25) 19(1.725,1.75)
  rect 0.3x0.3 smd paste-0.15 mask+0: 21(0,0)
  Top Layer region: 0.16,2.65 0.16,1.925 -0.16,1.925 -0.16,2.65 -0.39,2.65 -0.39,1.525 -1.025,1.525 -1.025,-1.525 -0.39,-1.525 -0.39,-2.65 -0.16,-2.65 -0.16,-1.925 0.16,-1.925 0.16,-2.65 0.39,-2.65 0.39,-1.525 1.025,-1.525 1.025,1.525 0.39,1.525 0.39,2.65
  silkscreen extent -1.97,-2.48 1.98,3.25, body extent -1.82,-2.33 1.83,2.32, height 1
S2B-PH-K-S [mm]
  round 1.5 hole 0.7: 1(0,0) 2(2,0)
  silkscreen extent -1.95,-1.35 3.95,6.25
SINGLE_3_1.27mm [mm] "Connector; Header; 3 Position"
  rect 1x1.5 smd: 1(0,0) 2(1.27,0) 3(2.54,0)
  silkscreen extent -1.05,-0.9 3.17,0.9
SM/C_0402 [mil]
  rect 22x22 smd: 1(-21,0) 2(21,0)
  silkscreen extent -41,-20 41,20, body extent -20,-10 20,10, height 20
SM/C_0603 [mil]
  rect 32x38 smd: 1(-28,0) 2(28,0)
  silkscreen extent -55,-29 54,29, body extent -31,-16 31,15, height 31
SM/C_0805 [mil]
  rect 50x50 smd: 1(-42,0) 2(42,0)
  silkscreen extent -78,-36 78,36, body extent -39,-24 39,23, height 47
SM/C_0805_POL [mil]
  rect 50x50 smd: 1(-42,0) 2(42,0)
  silkscreen extent -98,-36 78,55, body extent -39,-24 39,23, height 47
SM/D_0603 [mm] "Diode Package 0603"
  rect 0.8x0.6 smd: 1(0.85,0) 2(-0.85,0)
  silkscreen extent -0.9,-0.5 0.9,0.5, body extent -0.9,-0.5 0.9,0.5, height 0.85
SM/L_0402 [mil]
  rect 22x22 smd: 1(-21,0) 2(21,0)
  silkscreen extent -41,-20 41,20, body extent -20,-10 20,10, height 20
"SM/L_0603 (1608)" [mil]
  rect 32x38 smd: 1(-28,0) 2(28,0)
  silkscreen extent -55,-29 54,29, body extent -31,-16 32,16, height 35
SM/R_0402 [mil]
  rect 22x22 smd: 1(-21,0) 2(21,0)
  silkscreen extent 0,-20 0,20, body extent -19,-10 20,10, height 15
SM/R_0603 [mil]
  rect 32x38 smd: 1(-28,0) 2(28,0)
  silkscreen extent 0,-29 0,29, body extent -31,-16 32,16, height 21
SON-6_DRV [mm] "SON-6 DRV (TPS73533)"
  round 0.5 hole 0.3: 0(1.05,-1.05) 0(1.05,-0.25)
  rect 1x1.6 smd: 0(1.05,-0.65)
  rect 0.7x0.3 smd: 1(0,0) 2(0,-0.65) 3(0,-1.3) 4(2.1,-1.3) 5(2.1,-0.65) 6(2.1,0)
  silkscreen extent -0.75,-1.63 2.63,0.55
SON-8_DRB [mm] "SON-8 DRB (TPS7A8001)"
  round 0.5 hole 0.3: 0(1.075,-0.475) 0(1.075,-1.475) 0(1.475,-0.975) 0(1.875,-1.475) 0(1.875,-0.475)
  rect 0.28x1.225 smd: 0(1.15,0.313) 0(1.15,-2.263) 0(1.8,0.313)
  rect 1.5x1.75 smd: 0(1.475,-0.975)
  rect 0.28x1.225 smd paste+0: 0(1.8,-2.263)
  rect 0.85x0.35 smd: 1(0,0) 2(0,-0.65) 3(0,-1.3) 4(0,-1.95) 5(2.95,-1.95) 6(2.95,-1.3) 7(2.95,-0.65) 8(2.95,0)
  silkscreen extent -0.6,-3.05 3.55,1.1
SOT23 [mm] "SOT23, 3-Leads, Body 2,90x2,45mm, Pitch 0,95mm, IPC Medium Density"
  rect 1.3x0.6 smd: 1(-1.05,0.95) 2(-1.05,-0.95) 3(1.05,0)
  silkscreen extent -1.17,-1.5 0.7,1.93, body extent -0.7,-1.5 0.7,1.5, height 1.1
SOT23_0.915 [mm]
  rect 1.5x0.6 smd: 1(-0.925,0.95) 2(-0.925,-0.95) 3(0.925,0)
  silkscreen extent -1.05,-1.5 0.7,1.87, body extent -1.4,-1.45 1.4,1.45, height 1.3
SOT-323 [mm]
  rect 0.7x0.9 smd: 1(-0.65,-0.95) 2(0.65,-0.95) 3(0,0.95)
  silkscreen extent -1.15,-1.55 1.15,1.55
SOT-363_0.95 [mm] "TSOT-23, 6-Leads, Body 2.90x1.63mm, Pitch 0.95mm, IPC Medium Density"
  rect 1.25x0.6 smd: 1(-1.325,0.95) 2(-1.325,0) 3(-1.325,-0.95) 4(1.325,-0.95) 5(1.325,0) 6(1.325,0.95)
  silkscreen extent -2.1,-1.45 0.67,1.9, body extent -1.43,-1.45 1.4,1.45, height 1
supersot_6 [mm]
  rect 1x0.7 smd: 1(-1.3,0.95) 2(-1.3,0) 3(-1.3,-0.95) 4(1.3,-0.95) 5(1.3,0) 6(1.3,0.95)
  silkscreen extent -1.42,-1.5 0.45,1.97, body extent -0.84,-1.5 0.84,1.5, height 1.1
Taoglas-GLA.01 [mm]
  rect 0.6x1.3 smd: 1(0,0) 2(0,-1.7)
  rect 0.6x3 smd: 3(5,-0.85)
  silkscreen extent -0.45,-2.5 5.45,0.8
TC2030-IDC [mm]
  round 2.3 hole 2.375 unplated: 0(0,3.04) 0(0,-3.04) 0(3.175,3.04) 0(3.175,-3.04)
  round 0.9 hole 0.995 unplated: 0(0,0) 0(5.08,-1.016) 0(5.08,1.016)
  round 0.79 smd paste-0.6: 1(1.27,-0.635) 2(1.27,0.635) 3(2.54,-0.635) 4(2.54,0.635) 5(3.89,-0.635) 6(3.81,0.635)
  silkscreen extent -1.4,-4.4 5.71,4.4
Test_PAD_HOLE_3x3mm [mm]
  oct 3x3 hole 2.5: 0(0,0)
U.FL-R-SMT [mm]
  rect 1x1.05 smd: 1(0,0)
  rect 1.05x2.2 smd: 2(-1.475,1.525) 2(1.475,1.525)
  silkscreen extent -1.5,-0.18 1.5,2.92
W3102 [mm]
  rect 2.5x7.5 smd: 1(-2.6,0) 2(2.6,0)
  silkscreen extent -1,-3.9 1,3.9, body extent -3.6,-3.9 3.6,3.9, height 5.45
WE-WPCC [mm] "Wireless Power Charging  Receiver Coil"
  rect 1.5x1.5 hole 1: 1(0,0)
  round 1.5 hole 1: 2(2,0)
  silkscreen extent -1.14,-1.14 3.18,1.14

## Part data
ANT1: "GPS Loop Antenna"
ANT2: "Antenna", Manufacturer_Name="PulseLarsen Antennas", Mouser Part Number=673-W3102
C1 C4 C55: Supplier Part Number 1=445-1358-1-ND, Supplier Part Number 1b=445-1358-6-ND, Tolerance=10%, Voltage=16V
C2: Supplier Part Number 1=445-1420-1-ND, Supplier Part Number 1b=XXX, Tolerance=10%, Voltage=16V
C3: Supplier Part Number 1=490-1512-1-ND, Supplier Part Number 1b=490-1512-6-ND, Tolerance=10%, Voltage=50V
C5 C8 C15 C45 C48: Supplier Part Number 1=445-4112-1-ND, Supplier Part Number 1b=445-4112-6-ND, Tolerance=20%, Voltage=6.3V
C6: Supplier Part Number 1=445-14527-1-ND, Supplier Part Number 1b=445-14527-6-ND, Tolerance=10%, Voltage=10V
C7 C21 C67 C68: Supplier Part Number 1=490-3291-1-ND, Tolerance=5%, Voltage=25V
C9 C11 C43: Supplier Part Number 1=445-5987-1-ND, Supplier Part Number 1b=445-5987-6-ND, Tolerance=20%, Voltage=6.3V
C10 C12: Supplier Part Number 1=490-1351-1-ND, Supplier Part Number 1b=490-1351-6-ND, Tolerance=5%, Voltage=100V
C16: Supplier Part Number 1=445-1316-1-ND, Voltage=25V
C17 C18: library part CMP-2006-04063-1, Manufacturer="AVX Interconnect / Elco", Part Number=06031A8R0CAT2A
C19 C20: Supplier Part Number 1=712-1313-1-ND, Tolerance=5%, Voltage=50V
C26 C30 C31 C37 C47 C49: Supplier Part Number 1=445-1316-1-ND, Supplier Part Number 1b=445-1316-6-ND, Tolerance=10%, Voltage=25V
C27 C64: Supplier Part Number 1=709-1123-1-ND, Supplier Part Number 1b=709-1123-6-ND, Tolerance=5%, Voltage=50V
C28: library part CMP-2000-07531-1, "Chip Capacitor, 1 uF, +/- 10%, 50 V, -55 to 125 degC, 0603 (1608 Metric), RoHS, Tape and Reel", Capacitance=1uF, Case/Package=0603, Case Code (Metric)=1608, Dielectric=X7R, Manufacturer="Taiyo Yuden", Max Operating Temperature=125degC, Min Operating Temperature=-55degC, Package Description="2-Pin Surface Mount Device, Body 1.65 x 0.85 mm", Package Quantity=1, Package Reference=603, Tolerance=10%, Voltage Rating=50V
C29: library part CMP-2000-07531-1, "Chip Capacitor, 1 uF, +/- 10%, 50 V, -55 to 125 degC, 0603 (1608 Metric), RoHS, Tape and Reel", Case/Package=0603, Case Code (Metric)=1608, Dielectric=X7R, Manufacturer="Taiyo Yuden", Max Operating Temperature=125degC, Min Operating Temperature=-55degC, Package Description="2-Pin Surface Mount Device, Body 1.65 x 0.85 mm", Package Quantity=1, Package Reference=603, Tolerance=10%, Voltage Rating=50V
C34: library part CMP-2006-04681-1, Manufacturer="AVX Interconnect / Elco"
C38: Supplier Part Number 1=490-6229-1-ND, Supplier Part Number 1b=490-6229-6-ND, Tolerance=0.1pF, Voltage=50V
C40 L1 L2 L3 L6 L7 R17 R34 R35: Supplier Part Number 1=P0.0JCT-ND, Supplier Part Number 1b=P0.0JDKR-ND, Tolerance=1%
C42: Supplier Part Number 1=490-7753-1-ND, Supplier Part Number 1b=490-7753-6-ND, Tolerance=1%, Voltage=50V
C44: Supplier Part Number 1=445-1604-1-ND, Supplier Part Number 1b=445-1604-6-ND, Tolerance=10%, Voltage=16V
C50 C52: Supplier Part Number 1=445-5930-1-ND, Supplier Part Number 1b=445-5930-6-ND, Tolerance=10%, Voltage=50V
C51: Supplier Part Number 1=490-3297-1-ND, Supplier Part Number 1b=490-3297-6-ND, Tolerance=10%, Voltage=6.3V
C53 C54: Supplier Part Number 1=445-1604-1-ND, Voltage=25V
C56: Supplier Part Number 1=P16231CT-ND, Tolerance=20%, Voltage=6.3V
C57 C66: Supplier Part Number 1=490-3884-1-ND, Supplier Part Number 1b=490-3884-6-ND, Tolerance=10%, Voltage=50V
C58: Supplier Part Number 1=490-3287-1-ND, Supplier Part Number 1b=490-3287-6-ND, Tolerance=10%, Voltage=50V
C60: Supplier Part Number 1=490-10481-1-ND, Supplier Part Number 1b=490-10481-6-ND, Tolerance=10%, Voltage=16V
C61 C65: Supplier Part Number 1=399-7758-1-ND, Supplier Part Number 1b=399-7758-6-ND, Tolerance=5%, Voltage=50V
C62: Supplier Part Number 1=478-1118-1-ND, Supplier Part Number 1b=478-1118-6-ND, Tolerance=10%, Voltage=16V
C63: Supplier Part Number 1=490-1457-1-ND, Supplier Part Number 1b=490-1457-6-ND, Tolerance=5%, Voltage=50V
D1 D3: library part ONSC-D-K1A2-2, "Schottky Barrier Diode, 2-Pin SOD-523, Pb-Free, Tape and Reel", Manufacturer="On Semiconductor"
D2: library part D-4148-0603, Supplier Part Number 1=641-1001-1-ND, Supplier Part Number 1b=641-1001-6-ND
J1: library part "FTDI 3 pin"
J2: library part WPCC_COIL, Supplier Part Number 1=710-760308103206
J3: "ARM Cortex 10-pin Cable with 6-Pin TC2030 Plug-of-Nails Connector", Manufacturer=Tag-Connect, Supplier Part Number 1=TC2030-IDC-ND
J_ANT_GPS J_ANT_RF J_ANT_RF1 J_ANT_RF2 J_ANT_RF3 J_LNA_IN J_LNA_OUT: Supplier Part Number 1=H9161CT-ND
J_BAT: "JST, Through-Hole, Side entry type", Supplier Part Number 1=455-1719-ND
J_charge_5v: library part "charge 5v optionnel", "connecteur de charge 5v si jamais il y avais des problemes avec la charge par induction. (fils a souder directement sur le pcb, pas de connecteur externe)"
J_RF: library part conn_ant_RF
L4: Supplier Part Number 1=490-1080-1-ND, Supplier Part Number 1b=490-6561-6-ND, Tolerance=0.3nH
L5: Supplier Part Number 1=445-2987-1-ND, Tolerance=20%
LED1 LED4 LED7: Supplier Part Number 1=P11475DKR-ND
LED2 LED5: Supplier Part Number 1=P11480DKR-ND
LED3: Supplier Part Number 1=P11478DKR-ND
LED6: Supplier Part Number 1=P13681CT-ND
M1: library part NEO-M8P, "NEW !! GNSS module for GPS/QZSS, GLONASS"
Micro_SD: Supplier Part Number 1=101-00660-68-6-6-ND
Q1 Q3: "MOSFET N-CH 50V 200MA SOT23-3", Manufacturer="Diodes Inc", Supplier Part Number 1=BSS138-FDICT-ND, Supplier Part Number 1b=BSS138-FDIDKR-ND
Q2: library part PMOS-DMP2160UW-1.5A, "Low RDS(ON)", Supplier Part Number 1=DMP2160UWDICT-ND
Q4: library part IRLML6402, "MOSFET P-CH 20V 3.7A SOT-23", Manufacturer="International Rectifier", Supplier Part Number 1=IRLML6402PBFCT-ND
Q5: Supplier Part Number 1=FDC6304PCT-ND, Supplier Part Number 1b=FDC6304PDKR-ND
R1 R53: Supplier Part Number 1=P62KDBCT-ND, Supplier Part Number 1b=P62KDBDKR-ND, Tolerance=0.1%
R2 R16 R20 R44 R47: Supplier Part Number 1=P100KHCT-ND, Supplier Part Number 1b=P100KHDKR-ND, Tolerance=1%
R3 R7 R8 R9: Supplier Part Number 1=P10KDBCT-ND, Supplier Part Number 1b=P10KDBDKR-ND, Tolerance=0.1%
R4 R5 R6 R37: Supplier Part Number 1=P2.70KHCT-ND, Tolerance=1%
R10 R11 R12 R24 R25 R30 R33 R40 R49: Supplier Part Number 1=P10.0KHCT-ND, Supplier Part Number 1b=P10.0KHDKR-ND, Tolerance=1%
R19 R27: Supplier Part Number 1=P470HCT-ND, Supplier Part Number 1b=P470HDKR-ND, Tolerance=1%
R21 R22: Supplier Part Number 1=P100KDBCT-ND, Supplier Part Number 1b=P100KDBDKR-ND, Tolerance=0.1%
R23: Supplier Part Number 1=P390KHCT-ND, Supplier Part Number 1b=P390KHDKR-ND, Tolerance=1%
R26: Supplier Part Number 1=P20.0KHCT-ND, Supplier Part Number 1b=P20.0KHDKR-ND, Tolerance=1%
R28 R41: Supplier Part Number 1=P100HCT-ND, Supplier Part Number 1b=P100HDKR-ND, Tolerance=1%
R29: library part R-nc-0603
R31: Supplier Part Number 1=P0.0GCT-ND, Supplier Part Number 1b=P0.0GDKR-ND, Tolerance=1%
R36: Supplier Part Number 1=P470KHCT-ND, Supplier Part Number 1b=P470KHDKR-ND, Tolerance=1%
R38: Supplier Part Number 1=P2.43KHCT-ND, Tolerance=1%
R39: Supplier Part Number 1=P422HCT-ND, Supplier Part Number 1b=P422HDKR-ND, Tolerance=1%
R42: Supplier Part Number 1=P200HCT-ND, Supplier Part Number 1b=P200HDKR-ND, Tolerance=1%
R48 R51: Supplier Part Number 1=P1.00MHCT-ND, Supplier Part Number 1b=P1.00MHDKR-ND, Tolerance=1%
R50: Supplier Part Number 1=P47.0HCT-ND, Supplier Part Number 1b=P47.0HDKR-ND, Tolerance=1%
U1: Supplier Part Number 1=296-24288-1-ND
U2: Supplier Part Number 1=296-30110-1-ND
U3: "Stand-Alone Linear Li-Ion/Li-Polymer Charge Management Controller with Power-Good Output, 4.2V, 10-Pin DFN, Industrial Temperature", Supplier Part Number 1=MCP73833T-AMI/MF-ND
U4: library part CMP-2000-07520-1, "RF System on a Chip, 1.7 to 3.6 V, -40 to 85 degC, 73-Pin AQFN, RoHS, Tape and Reel", Manufacturer="Nordic Semiconductor", Package Description="73-Pin Array Quad Flat No-lead Package, Body 7 x 7 mm, Pitch 0.5 mm", Package Reference=AQFN
U5: Supplier Part Number 1=296-37710-1-ND
U6: "IC LOAD SWITCH INT 20VIN SSOT-6", Manufacturer="Fairchild Semiconductor", Supplier Part Number 1=FDC6330LCT-ND
U7: "Silicon Germanium Low Noise Amplifier for Global Navigation Satellite Systems (GNSS), 1550 - 1615 MHz, 20 dB Gain, TSLP-6-2, Green", Frequency (f)="1550 - 1615 MHz", Manufacturer=Infineon, Supplier Part Number 1="BGA 725L6 E6327CT-ND"
U8: "SAW filter", Frequency (f)="1550 - 1615 MHz", Manufacturer=Infineon, PartNumber=BGA725L6, Supplier Part Number 1=495-3910-1-ND
U9: library part bq5105xB, Supplier Part Number 1=296-35066-1-ND
U10: "Pour la conception du module RF"
U11: library part AS2953A
U12: library part CMP-0859-00252-3, "Single Inverter, DCK0005A, LARGE T&R", F @ Nom Voltage(Max)(Mhz)=150, Generic Part Number=SN74LVC1G04, ICC @ Nom Voltage(Max)(mA)=0.01, Manufacturer="Texas Instruments", Operating Temperature Range(C)="-40 to 125,-40 to 85", Rating=Catalog, tpd @ Nom Voltage(Max)(ns)=7.5,5.2,4.2,3.7, Voltage(Nom)(V)=1.8,2.5,3.3,5
U13: "ble ant 2.4 GHz"
U15 U16: "Hall Effect Sensor"
X1: library part CMP-0449-00001-2, "Crystal, 32 MHz, 8 pF, -10 to 70 degC, Surface Mount 2.5 x 2.0 mm", Frequency Range="32000 kHz", Load Capacitance="8 pF", Manufacturer=Kyocera, Motional Series Resistance="50 ohm (max)", Operating Temperature="-10 to 70 degC"
Y2: Supplier Part Number 1=CTX1160DKR-ND

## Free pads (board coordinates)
  round 3.5 hole 3.5: 1(6.756,57.444) 1(7.731,3.414) 1(88.649,2.473) 1(97.029,57.504)
  round 2 hole 1: 2(32.45,6.2) 2(32.5,58.6)

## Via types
v1: diameter 0.5, hole 0.3, Top Layer to Bottom Layer, 281 vias
v2: diameter 0.25, hole 0.15, Top Layer to Bottom Layer, 274 vias
v3: diameter 0.35, hole 0.2, Top Layer to Bottom Layer, 58 vias
v4: diameter 0.5, hole 0.2, Top Layer to Bottom Layer, 30 vias
v5: diameter 0.4, hole 0.25, Top Layer to Bottom Layer, 20 vias
v6: diameter 0.8, hole 0.5, Top Layer to Bottom Layer, 2 vias
v7: diameter 0.5, hole 0.35, Top Layer to Bottom Layer, 1 vias

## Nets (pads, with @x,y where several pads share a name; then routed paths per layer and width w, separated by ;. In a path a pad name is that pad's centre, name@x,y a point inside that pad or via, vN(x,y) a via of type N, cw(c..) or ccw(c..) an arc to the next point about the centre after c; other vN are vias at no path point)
/CHG: LED7.2 Q4.1 U9.7 | length 54.5
  Top Layer w0.2: LED7.2@30.875,2.55 30.875,1.925 30.575,1.625 28.35,1.625 27.5,2.475 27.5,6.6 35.75,14.85 35.75,28.45 36.725,29.425 v2(36.725,35.719) ; v2(40.5,35.719) 45.756,35.719 Q4.1@45.825,35.65 ; Q4.1@46.175,35.7 46.325,35.85 47.751,35.85 48.351,36.45 U9.7@49.65,36.45
  Bottom Layer w0.2: v2(36.725,35.719) v2(40.5,35.719)
AG_1: C22.2 L1.1 M1.11 | length 3.7
  Top Layer w0.15: C22.2@85.642,36.4 C22.2@85.742,36.5
  Top Layer w0.6: M1.11@83.275,36.4 85.112,36.4 ccw(c85.112,37.063) 85.775,37.063 L1.1@85.775,37.733
AG_2: C23.2 J_LNA_OUT.1 L1.2 U7.3 | length 6.5
  Top Layer w0.3: 85.742,44.733 U7.3@85.754,45.267
  Top Layer w0.6: C23.2@85.742,40 J_LNA_OUT.1@85.742,43.965 85.742,44.733 ; L1.2@85.775,38.8 C23.2@85.775,40
AG_3: C24.2 L4.1 U7.5 | length 2.7
  Top Layer w0.3: U7.5@86.154,45.667 86.678,45.667
  Top Layer w0.6: 86.678,45.667 C24.2@87.575,45.667 L4.1@88.808,45.667
AG_4: C25.2 J_LNA_IN.1 L4.2 R34.1 | length 6.1
  Top Layer w0.6: L4.2@89.908,45.7 91.175,45.7 C25.2@91.177,45.7 ; C25.2@91.175,45.667 92.447,45.667 92.493,45.621 R34.1@95.993,45.621
AG_5: R34.2 U8.4 | length 0.9
  Top Layer w0.6: U8.4@97.142,44.71 R34.2@97.142,45.6
AG_6: R35.1 U8.1 | length 0.8
  Top Layer w0.6: R35.1@97.515,42.698 97.515,43.5
AG_7: C38.2 J_ANT_GPS.1 R17.1 R35.2 | length 6.1
  Top Layer w0.3: C38.2@96,36.938 97.196,36.938
  Top Layer w0.6: R17.1@97.475,36.658 J_ANT_GPS.1@97.475,37.938 R35.2@97.475,41.592
AG_8: ANT1.2 C39.2 R17.2 | length 2.9
  Top Layer w0.15: ANT1.2@97.475,34.25 ccw(c97.5,34.25) ANT1.2@97.5,34.225
  Top Layer w0.3: C39.2@96,35.592 R17.2@97.475,35.592
  Top Layer w0.6: ANT1.2@97.475,34.25 R17.2@97.475,35.592
ANT_1: C13.2 J_ANT_RF3.1 L3.1 U10.21 | length 12.4
  Top Layer w0.254: L3.1@8.504,10.225 C13.2@8.504,11.275
  Top Layer w0.6: L3.1@8.258,10.025 v6(9.433,10.025)
  Bottom Layer w0.6: v6(9.433,10.025) 12.687,10.025 ccw(c12.687,11.022) 13.684,11.022 13.684,13.975 U10.21@13.684,16.4
ANT_2: C14.2 J_ANT_RF.1 J_RF.1 L3.2 | length 6.9
  Top Layer w0.254: L3.2@6.912,10.025 C14.2@6.912,11.367
  Top Layer w0.6: J_RF.1@1.375,10.043 J_ANT_RF.1@2.958,10.043 ; J_ANT_RF.1@2.958,10.125 cw(c2.958,10.025) J_ANT_RF.1@3.058,10.025 L3.2@6.912,10.025
CHG: Q4.3 R36.2 U4.T23 | length 75.6
  Top Layer w0.2: v2(44.575,34.6) 44.675,34.7 Q4.3@47.675,34.7 48.125,34.7 48.298,34.527 48.298,33.196 48.894,32.6 48.894,31.703 48.414,31.223 48.398,31.223 47.486,30.311 R36.2@47.486,30.3 ; v2(52.619,3.2) 52.619,4.619 53.312,5.312 v2(53.312,7.325)
  Bottom Layer w0.2: v2(44.575,34.6) 43.075,33.1 43.075,15.188 46.144,12.119 48.519,12.119 v2(53.312,7.325) ; v2(52.619,3.2) 52.55,3.2 54.9,0.85 67.475,0.85 70.625,4 70.625,7.8 69.575,8.85 67.85,8.85 67.4,8.4 v2(66.725,8.4)
EN_VCC_uC_NFC: D3.2 U11.2 | length 11
  Top Layer w0.2: U11.2@60.83,23.225 60.755,23.3 60.323,23.3 60.075,23.548 60.075,25.275 60.65,25.85 61.64,25.85 62.55,24.94 D3.2@67.825,24.94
